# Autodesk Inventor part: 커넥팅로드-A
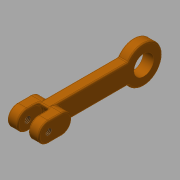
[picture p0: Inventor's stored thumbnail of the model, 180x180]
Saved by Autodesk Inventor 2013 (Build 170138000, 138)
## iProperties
Created: 2018-01
Part Number: 커넥팅로드-A
Material: 알루미늄 6061
Document SubType Name: Modeling
Designer: mduedu
Density: 1 g/cm^3
Author: mduedu
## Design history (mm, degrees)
sketch "스케치1"
  geometry: L1 (0, 0)-(0, 40); L2 (3.75, 40)-(3.75, 5.911); L3 (-3.75, 40)-(-3.75, 5.911); A1 r 7 centre (0, 0) between (3.75, 5.911) and (-3.75, 5.911); A2 r 3.75 centre (0, 40) between (3.75, 40) and (-3.75, 40); 1 further point
  constraints: 6 end point, 4 point on circle, 2 centre point, 2 coincident, 2 parallel, 2 tangent, 1 vertical
  dimensions: "d1" = 40 distance of L1.start L1.end; "d2" = 7.5 diameter of A2; "d3" = 14 diameter of A1
extrude "돌출1" new body sketch "스케치1" stored distance "d4" = 4; taper "d5" = 0 deg
sketch "스케치2"
  geometry: L1 (-3.75, 40)-(-3.75, 35); L2 (3.75, 40)-(3.75, 35); A1 r 3.75 centre (0, 40) between (3.75, 40) and (-3.75, 40) reference; A2 r 3.75 centre (0, 40) between (3.75, 40) and (-3.75, 40); A3 r 3.75 centre (0, 35) between (-3.75, 35) and (3.75, 35); 1 further point
  constraints: 4 end point, 4 point on circle, 2 centre point, 2 tangent, 1 coincident, 1 equal radius, 1 point on line, 1 vertical alignment
  dimensions: "d6" = 5 distance of A3.centre A1.centre
extrude "돌출2" join sketch "스케치2" stored distance "d7" = 12; taper "d8" = 0 deg
sketch "스케치3"
  geometry: L1 (3.75, 40)-(3.75, 38); L2 (-3.75, 40)-(-3.75, 38); A1 r 3.75 centre (0, 40) between (3.75, 40) and (-3.75, 40) reference; A2 r 3.75 centre (0, 40) between (3.75, 40) and (-3.75, 40); A3 r 3.75 centre (0, 38) between (-3.75, 38) and (3.75, 38); 1 further point
  constraints: 4 end point, 4 point on circle, 3 tangent, 2 centre point, 1 coincident, 1 equal radius, 1 parallel, 1 point on line
  dimensions: "d9" = 2 distance of A3.centre A1.centre
extrude "돌출3" cut sketch "스케치3" stored distance "d10" = 4; taper "d11" = 0 deg
fillet "모깎기5" dims "d16" = 0.5
fillet "모깎기6" dims "d17" = 0.5
fillet "모깎기7" dims "d18" = 0.5
fillet "모깎기8" dims "d19" = 0.5
hole "구멍1" diameter "d22" = 7.5; stored, may be unused: countersink angle "d26" = 90 deg, drill point angle "d28" = 118 deg; dims "d20" = 10, "d21" = 10, "d23" = 6, "d24" = 4, "d25" = 2, "d27" = 8
sketch "스케치4"
  geometry: A1 r 3.75 centre (40, 0) between (40, -3.75) and (40, 3.75) reference; 2 further points
  constraints: 1 coincident
sketch "스케치5"
  geometry: 1 further point
  constraints: 1 other
hole "구멍2" sketch "스케치5" at (40, 0) diameter "d29" = 2.459; stored, may be unused: countersink angle "d33" = 90 deg, drill point angle "d35" = 0 deg; dims "d30" = 6, "d31" = 4, "d32" = 2, "d34" = 8
sketch "스케치6"
  geometry: 1 further point
  constraints: 1 other
hole "구멍4" sketch "스케치6" at (-40, 0) diameter "d36" = 2.459; stored, may be unused: countersink angle "d40" = 90 deg, drill point angle "d42" = 0 deg; dims "d37" = 6, "d38" = 4, "d39" = 2, "d41" = 8
node "솔리드1"
